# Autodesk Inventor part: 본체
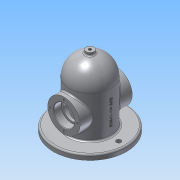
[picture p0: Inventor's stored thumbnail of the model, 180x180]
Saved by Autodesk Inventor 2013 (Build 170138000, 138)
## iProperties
Created: 2019-11
Part Number: 본체
Material: 알루미늄 6061
Document SubType Name: Modeling
Designer: Administrator
Density: 2.71 g/cm^3
Mass: 1110.22 g
Surface Area: 883.263 cm^2
Volume: 409.674 cm^3
Author: Administrator
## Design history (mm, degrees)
sketch "스케치1"
  geometry: C1 r 70 at (0, 0); 1 further point
  constraints: 1 centre point, 1 coincident
  dimensions: "d0" = 140 diameter of C1
extrude "돌출1" new body sketch "스케치1" distance "d1" = 10; taper "d2" = 0 deg
sketch "스케치2"
  geometry: C1 r 70 at (0, 0) reference; C2 r 40 at (0, 0)
  constraints: 1 centre point, 1 coincident
  dimensions: "d3" = 80 diameter of C2
extrude "돌출2" join sketch "스케치2" distance "d4" = 120; taper "d5" = 0 deg
sketch "스케치3"
  geometry: L1 (-70, 0)-(70, 0) reference; L2 (-40, 10)-(40, 10) reference; C1 r 31 at (0, 50); 1 further point
  constraints: 1 centre point, 1 vertical alignment
  dimensions: "d7" = 62 diameter of C1; "d8" = 40 distance from line of L2 C1.centre
extrude "돌출3" join sketch "스케치3" stored distance "d9" = 100; taper "d10" = 0 deg
sketch "스케치4"
  geometry: C1 r 31 at (0, 0) reference; C2 r 20 at (0, 0); 1 further point
  constraints: 1 centre point, 1 coincident
  dimensions: "d11" = 40 diameter of C2
extrude "돌출4" cut sketch "스케치4" distance "d12" = 15; taper "d13" = 0 deg
sketch "스케치5"
  geometry: C1 r 20 at (0, 0) reference; C2 r 16.5 at (0, 0); 1 further point
  constraints: 1 centre point, 1 coincident
  dimensions: "d14" = 33 diameter of C2
extrude "돌출5" cut sketch "스케치5" stored distance "d15" = 15; taper "d16" = 0 deg
fillet "모깎기1" dims "d17" = 40
sketch "스케치7"
  geometry: L1 (40, 90)-(-40, 90) reference; L2 (-70, 0)-(70, 0) reference; 1 further point
  node "투영된 루프1"
sketch "스케치8"
  geometry: L1 (0, 0)-(30, 0); L2 (30, 0)-(30, 90); L3 (0, 120)-(0, 120); L4 (0, 120)-(0, 0); A1 r 30 centre (0, 90) between (30, 90) and (0, 120); 1 further point
  constraints: 8 end point, 2 parallel, 2 point on circle, 2 point on line, 2 tangent, 1 centre point, 1 horizontal, 1 perpendicular
  dimensions: "d18" = 30 distance of L3.end point (30, 120); "d19" = 120 distance of point (30, 120) L1.end; "d20" = 30 radius of A1
revolve "회전1" sketch "스케치8" stored, may be unused: angle "d21" = 90 deg
sketch "스케치9"
  geometry: C1 r 20 at (0, 0) reference; C2 r 20 at (0, 0) reference; C3 r 31 at (0, 0) reference; 2 further points
  constraints: 1 vertical alignment
  dimensions: "d22" = 26 distance of point (0, 26) C1.centre
hole "구멍1" sketch "스케치9" at (0, 26) diameter "d23" = 3.242; stored, may be unused: countersink angle "d27" = 90 deg, drill point angle "d29" = 118 deg; dims "d24" = 8, "d25" = 4, "d26" = 2, "d28" = 10
sketch "스케치10"
  geometry: C1 r 30 at (0, 0) reference; C2 r 70 at (0, 0) reference; A1 r 55 centre (0, 0) between (55, 0) and (-55, 0)
  constraints: 2 horizontal alignment, 2 point on circle, 1 centre point, 1 coincident
  dimensions: "d33" = 110 diameter of A1
hole "구멍2" sketch "스케치10" at (55, 0), (-55, 0) diameter "d34" = 9; stored, may be unused: countersink angle "d38" = 90 deg, drill point angle "d40" = 118 deg; dims "d35" = 8, "d36" = 4, "d37" = 2, "d39" = 10
node "작업 평면1"
sketch "스케치11"
  geometry: C1 r 40 at (0, 0) reference; C2 r 7.5 at (0, 0); 1 further point
  constraints: 1 centre point, 1 coincident
  dimensions: "d42" = 15 diameter of C2
extrude "돌출6" join sketch "스케치11" stored distance "d43" = 120; taper "d44" = 0 deg
sketch "스케치12"
  geometry: C1 r 7.5 at (0, 0) reference; 1 further point
  constraints: 1 coincident
hole "구멍3" sketch "스케치12" at (0, 0) diameter "d45" = 5.188; stored, may be unused: countersink angle "d49" = 90 deg, drill point angle "d51" = 118 deg; dims "d46" = 19, "d47" = 4, "d48" = 2, "d50" = 20
node "작업 평면2"
sketch "스케치13"
  geometry: L1 (-70, 0)-(70, 0) reference; 2 further points
  constraints: 1 vertical alignment, 1 other
  dimensions: "d53" = 50 distance from line of L1 point (0, 50)
feature "엠보싱1" sketch "스케치13" dims "d54" = 0.5, "d55" = 0
fillet "모깎기2" dims "d56" = 3
chamfer "모따기2" distance "d60" = 1; stored, may be unused: second distance "d61" = 2, angle "d62" = 45 deg
fillet "모깎기3" dims "d63" = 0.3
fillet "모깎기4" dims "d64" = 3
node "솔리드1"
mirror "대칭1"
pattern_circular "원형 패턴1" dims angle "d31" = 360 deg
mirror "대칭2"
node "투영된 루프2"
node "투영된 루프3"
other parameters: "d41" = 135
